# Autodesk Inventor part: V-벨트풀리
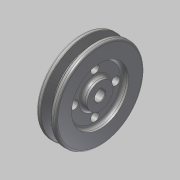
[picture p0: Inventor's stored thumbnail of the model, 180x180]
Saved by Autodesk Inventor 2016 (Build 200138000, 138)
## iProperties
Created: 2015-09
Part Number: V-벨트풀리
Material: 강철, 연강
Document SubType Name: Modeling
Designer: mduedu
Density: 1 g/cm^3
Appearance: 강철
Author: mduedu
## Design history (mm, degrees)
sketch "스케치1"
  geometry: L1 (-9.5, 0)-(9.5, 0); L2 (-9.5, 0)-(-9.5, 42.7); L3 (-9.5, 42.7)-(-4.877, 42.7); L4 (-4.877, 42.7)-(-1.953, 33.7); L5 (-1.953, 33.7)-(1.953, 33.7); L6 (1.953, 33.7)-(4.877, 42.7); L7 (4.877, 42.7)-(9.5, 42.7); L8 (9.5, 42.7)-(9.5, 0); L9 (0, 0)-(0, 33.7); L10 (-9.5, 40)-(9.5, 40); 3 further points
  constraints: 20 end point, 6 point on line, 3 perpendicular, 2 midpoint, 2 parallel, 2 symmetric about line, 1 coincident, 1 collinear, 1 equal length, 1 horizontal, 1 vertical, 1 vertical alignment
  dimensions: "d0" = 19 distance between parallel lines of L8 L2; "d5" = 6.3 distance between parallel lines of L5 L10; "d6" = 8 distance of point (4, 40) point (-4, 40); "d7" = 36 deg angle of L6 L4; "d40" = 2.7 distance between parallel lines of L10 L3; "d82" = 80 diameter of L10 L1; "d83" = 85.4 diameter of L3 L1 (derived)
revolve "회전1" sketch "스케치1" stored, may be unused: angle "d8" = 90 deg
sketch "스케치2"
  geometry: C1 r 12.5 at (0, 0); C2 r 27.5 at (0, 0); 1 further point
  constraints: 2 centre point, 2 coincident
  dimensions: "d9" = 25 diameter of C1; "d41" = 55 diameter of C2
extrude "돌출5" cut sketch "스케치2" distance "d42" = 5; taper "d43" = 0 deg
hole "구멍2" diameter "d46" = 10; stored, may be unused: countersink angle "d50" = 90 deg, drill point angle "d52" = 118 deg; dims "d47" = 6, "d48" = 4, "d49" = 2, "d51" = 8, "d84" = 10, "d85" = 10
sketch "스케치8"
  geometry: L1 (-1.5, 4.77)-(1.5, 4.77); L2 (1.5, 4.77)-(1.5, 6.4); L3 (1.5, 6.4)-(-1.5, 6.4); L4 (-1.5, 6.4)-(-1.5, 4.77); A1 r 5 centre (0, 0) between (-1.5, 4.77) and (1.5, 4.77) reference; 1 further point
  constraints: 8 end point, 2 parallel, 2 point on circle, 1 horizontal, 1 perpendicular
  dimensions: "d53" = 3 distance of L2.end L3.end; "d55" = 11.4 dimension on A1 L3
extrude "돌출6" cut sketch "스케치8" stored distance "d56" = 5; taper "d57" = 0 deg
fillet "모깎기5" dims "d71" = 2, "d72" = 1, "d73" = 0.5
fillet "모깎기7" dims "d75" = 3
fillet "모깎기8" dims "d76" = 3
sketch "스케치10"
  geometry: C1 r 35 at (0, 0); 1 further point
  constraints: 1 centre point, 1 coincident, 1 other
  dimensions: "d77" = 70 diameter of C1
extrude "돌출8" join sketch "스케치10" distance "d80" = 0.5; taper "d81" = 0 deg
chamfer "모따기4" distance "d88" = 0.5; stored, may be unused: second distance "d89" = 2, angle "d90" = 45 deg
sketch "스케치11" dims "d91" = 40
  geometry: C1 r 4 at (0, 20); 2 further points
  constraints: 2 vertical alignment, 1 centre point, 1 coincident, 2 other
  dimensions: "d92" = 8 diameter of C1
extrude "돌출9" cut sketch "스케치11" stored distance "d93" = 10; taper "d94" = 0 deg
node "솔리드1"
mirror "대칭2"
pattern_circular "원형 패턴2" dims angle "d96" = 360 deg
